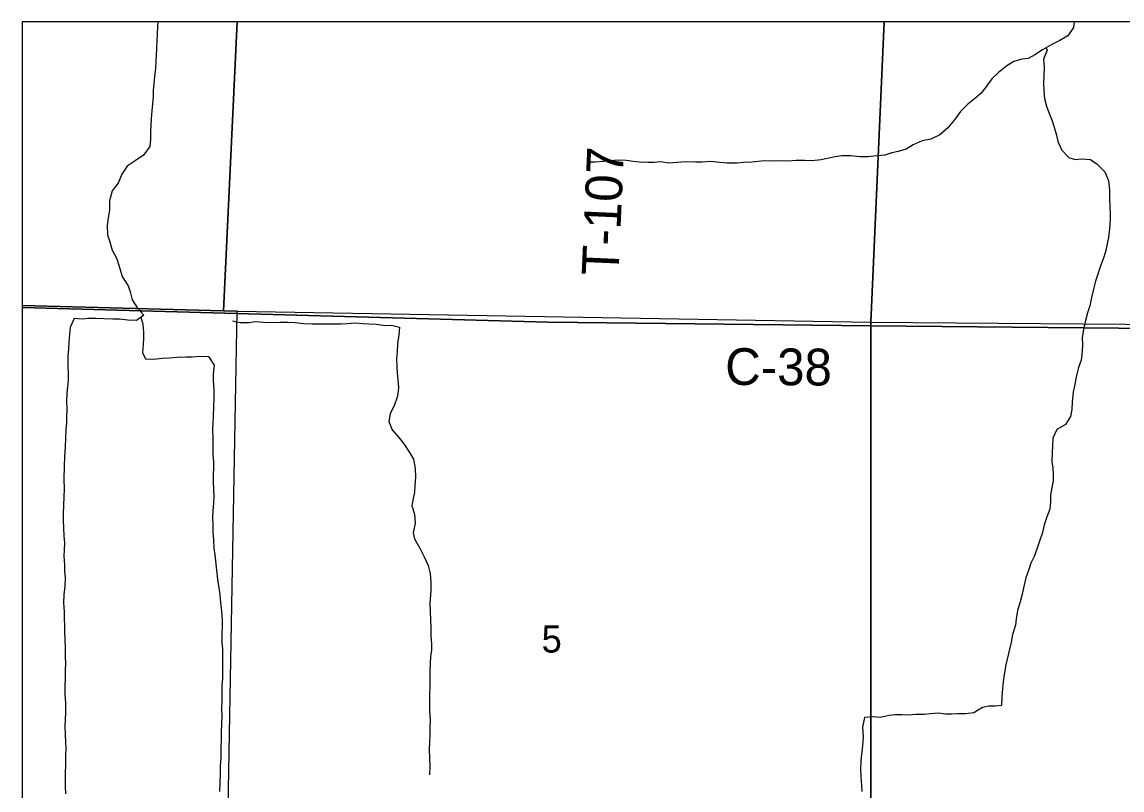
# Model space of a CAD drawing. Extents: x 1772825 to 1773716, y 1138558 to 1139032.
# Drawn here: x 1772825.358 to 1772826.207, y 1138563.767 to 1138564.359 of the extents above; entities that cross this region are included whole.
import ezdxf

# ---------------------------------------------------------------- set-up
doc = ezdxf.new("R2010")
doc.units = 0
for name, color, linetype in [('GM_X_County_Road_Text', 7, 'Continuous'), ('GM_X_Minor_River', 7, 'Continuous'), ('GM_X_Section', 7, 'Continuous'), ('GM_X_Section_Text', 7, 'Continuous'), ('GM_X_Township', 7, 'Continuous'), ('GM_X_Township_Road_Text', 7, 'Continuous')]:
    doc.layers.add(name, color=color, linetype=linetype)

msp = doc.modelspace()

# ---------------------------------------------------------------- linework, layer by layer
at = {"layer": 'GM_X_Minor_River'}
for points in [[(1772825.46264, 1138564.35945), (1772825.46245, 1138564.35612), (1772825.46224, 1138564.35005), (1772825.46202, 1138564.34493), (1772825.46162, 1138564.33868), (1772825.46141, 1138564.33394), (1772825.4612, 1138564.329), (1772825.4608, 1138564.32389), (1772825.4602, 1138564.31706), (1772825.45961, 1138564.31194), (1772825.45921, 1138564.30663), (1772825.459, 1138564.30189), (1772825.45859, 1138564.29639), (1772825.458, 1138564.2909), (1772825.45759, 1138564.28464), (1772825.45738, 1138564.2799), (1772825.45698, 1138564.27497), (1772825.45715, 1138564.26909), (1772825.45656, 1138564.2634), (1772825.4516, 1138564.25678), (1772825.44533, 1138564.25226), (1772825.43906, 1138564.24812), (1772825.43486, 1138564.24207), (1772825.43199, 1138564.23506), (1772825.42741, 1138564.22902), (1772825.4253, 1138564.22144), (1772825.42546, 1138564.21423), (1772825.42448, 1138564.20817), (1772825.42351, 1138564.20229)], [(1772826.16967, 1138564.35945), (1772826.16904, 1138564.35523), (1772826.16484, 1138564.3488), (1772826.15857, 1138564.34522), (1772826.1523, 1138564.34203), (1772826.14527, 1138564.33789), (1772826.13939, 1138564.33412), (1772826.13407, 1138564.3313), (1772826.12933, 1138564.33076), (1772826.12307, 1138564.32889), (1772826.11756, 1138564.3255), (1772826.11128, 1138564.32041), (1772826.10614, 1138564.31569), (1772826.10138, 1138564.30927), (1772826.09757, 1138564.30417), (1772826.09262, 1138564.3002), (1772826.08768, 1138564.29606), (1772826.08197, 1138564.29039), (1772826.07739, 1138564.28397), (1772826.07206, 1138564.27773), (1772826.06598, 1138564.27226), (1772826.05914, 1138564.26907), (1772826.05231, 1138564.26777), (1772826.04548, 1138564.26458), (1772826.03997, 1138564.26138), (1772826.0339, 1138564.25951), (1772826.02897, 1138564.2584), (1772826.02365, 1138564.25672), (1772826.0174, 1138564.25618), (1772826.01038, 1138564.25545), (1772826.00451, 1138564.25529), (1772825.99712, 1138564.25609), (1772825.9903, 1138564.25612), (1772825.98518, 1138564.25538), (1772825.98025, 1138564.25427), (1772825.97437, 1138564.25297), (1772825.96736, 1138564.25224), (1772825.96167, 1138564.25246), (1772825.95504, 1138564.25249), (1772825.94898, 1138564.25195), (1772825.94386, 1138564.25217), (1772825.93742, 1138564.25201), (1772825.93041, 1138564.25223), (1772825.92093, 1138564.25114), (1772825.91449, 1138564.25098), (1772825.90975, 1138564.25043), (1772825.90198, 1138564.25047), (1772825.89611, 1138564.25107), (1772825.88967, 1138564.25167), (1772825.88246, 1138564.25132), (1772825.87754, 1138564.25115)], [(1772826.14805, 1138564.33953), (1772826.14868, 1138564.33768), (1772826.146, 1138564.33068), (1772826.14635, 1138564.32423), (1772826.14633, 1138564.31797), (1772826.14592, 1138564.31247), (1772826.14609, 1138564.30621), (1772826.14663, 1138564.30033), (1772826.14831, 1138564.29444), (1772826.14999, 1138564.28969), (1772826.15262, 1138564.28304), (1772826.1543, 1138564.27829), (1772826.15598, 1138564.27221), (1772826.1571, 1138564.26708), (1772826.1601, 1138564.26062), (1772826.16557, 1138564.2549), (1772826.17049, 1138564.25336), (1772826.17523, 1138564.25372), (1772826.18224, 1138564.25331), (1772826.18734, 1138564.24968), (1772826.19338, 1138564.24377), (1772826.19619, 1138564.23712), (1772826.19692, 1138564.22991), (1772826.19689, 1138564.22308), (1772826.19705, 1138564.21663), (1772826.19741, 1138564.21169), (1772826.19739, 1138564.20695), (1772826.19679, 1138564.20013), (1772826.19619, 1138564.19311), (1772826.19503, 1138564.18819), (1772826.19406, 1138564.18307), (1772826.19252, 1138564.17795), (1772826.18965, 1138564.17038), (1772826.18792, 1138564.16489), (1772826.186, 1138564.1594), (1772826.18465, 1138564.15333), (1772826.18311, 1138564.14689), (1772826.18175, 1138564.14045), (1772826.18002, 1138564.13495), (1772826.17829, 1138564.12908), (1772826.17675, 1138564.12226), (1772826.17577, 1138564.11563), (1772826.17594, 1138564.11069), (1772826.17573, 1138564.10538), (1772826.17494, 1138564.09856), (1772826.17302, 1138564.09288), (1772826.17148, 1138564.08663), (1772826.17012, 1138564.07999), (1772826.16896, 1138564.07374), (1772826.16798, 1138564.06615), (1772826.16776, 1138564.06028), (1772826.16679, 1138564.05497), (1772826.16298, 1138564.04873), (1772826.15633, 1138564.04497), (1772826.15308, 1138564.03834), (1772826.15286, 1138564.03265), (1772826.15265, 1138564.02715), (1772826.15243, 1138564.02032), (1772826.15317, 1138564.0152), (1772826.15353, 1138564.01045), (1772826.15332, 1138564.00533), (1772826.15235, 1138564.00003), (1772826.15137, 1138563.99415), (1772826.15135, 1138563.98903), (1772826.15076, 1138563.98334), (1772826.14827, 1138563.97672), (1772826.14635, 1138563.97122), (1772826.14519, 1138563.96554), (1772826.14288, 1138563.95872), (1772826.14097, 1138563.95323), (1772826.13866, 1138563.94698), (1772826.13618, 1138563.94187), (1772826.13464, 1138563.93676), (1772826.13234, 1138563.93032), (1772826.1308, 1138563.92387), (1772826.12944, 1138563.91781), (1772826.1279, 1138563.91194), (1772826.12598, 1138563.90512), (1772826.125, 1138563.89867), (1772826.12423, 1138563.89393), (1772826.12211, 1138563.88674), (1772826.12095, 1138563.88086), (1772826.11689, 1138563.86324), (1772826.11573, 1138563.85585), (1772826.11494, 1138563.85016), (1772826.11435, 1138563.84504), (1772826.11376, 1138563.83821), (1772826.11354, 1138563.83195), (1772826.10861, 1138563.83141), (1772826.10387, 1138563.83143), (1772826.09894, 1138563.83032), (1772826.09229, 1138563.82636), (1772826.08566, 1138563.82545), (1772826.07978, 1138563.82548), (1772826.07505, 1138563.82531), (1772826.07031, 1138563.82533), (1772826.065, 1138563.82593), (1772826.05875, 1138563.82539), (1772826.05401, 1138563.82503), (1772826.04738, 1138563.82506), (1772826.04169, 1138563.82433)], [(1772825.87754, 1138564.25115), (1772825.87034, 1138564.25157), (1772825.86332, 1138564.25103), (1772825.85669, 1138564.25049), (1772825.85063, 1138564.25147), (1772825.8457, 1138564.25093), (1772825.84059, 1138564.25095), (1772825.83434, 1138564.25136), (1772825.82941, 1138564.25176), (1772825.82411, 1138564.25255), (1772825.81748, 1138564.25277), (1772825.80648, 1138564.25168), (1772825.80004, 1138564.25114), (1772825.7936, 1138564.25136)], [(1772825.42351, 1138564.20229), (1772825.42386, 1138564.19508), (1772825.42554, 1138564.18976), (1772825.42741, 1138564.1833), (1772825.43117, 1138564.17665), (1772825.43341, 1138564.16924), (1772825.43509, 1138564.16297), (1772825.4398, 1138564.15593), (1772825.44129, 1138564.15118), (1772825.44297, 1138564.1451), (1772825.44711, 1138564.13863), (1772825.45182, 1138564.13311), (1772825.44612, 1138564.12896), (1772825.43968, 1138564.12918), (1772825.43324, 1138564.12997), (1772825.42794, 1138564.13), (1772825.42112, 1138564.13022), (1772825.41486, 1138564.13063), (1772825.40899, 1138564.13066), (1772825.40425, 1138564.13011), (1772825.39819, 1138564.13071), (1772825.39513, 1138564.12352), (1772825.39454, 1138564.1184), (1772825.39413, 1138564.11214), (1772825.39373, 1138564.1074), (1772825.39314, 1138564.10095), (1772825.3933, 1138564.0945), (1772825.39365, 1138564.08767), (1772825.39363, 1138564.08293), (1772825.39304, 1138564.07781), (1772825.39245, 1138564.07288), (1772825.39223, 1138564.067), (1772825.39239, 1138564.06036), (1772825.39218, 1138564.05505), (1772825.39216, 1138564.04993), (1772825.39176, 1138564.04519), (1772825.39154, 1138564.03798), (1772825.39132, 1138564.03173), (1772825.39072, 1138564.02376), (1772825.39031, 1138564.01656), (1772825.39027, 1138564.0065), (1772825.39043, 1138563.9991), (1772825.39021, 1138563.99285), (1772825.38999, 1138563.9864), (1772825.38977, 1138563.97957), (1772825.38975, 1138563.97464), (1772825.38992, 1138563.96913), (1772825.39027, 1138563.96287), (1772825.39063, 1138563.95756), (1772825.39041, 1138563.95206), (1772825.3902, 1138563.94732), (1772825.39074, 1138563.9403), (1772825.39072, 1138563.93556), (1772825.39108, 1138563.93024), (1772825.39086, 1138563.92398), (1772825.39007, 1138563.91735), (1772825.39005, 1138563.91128), (1772825.3904, 1138563.90407), (1772825.39056, 1138563.89857), (1772825.39073, 1138563.89382), (1772825.39071, 1138563.88908), (1772825.39106, 1138563.88301), (1772825.39122, 1138563.87599), (1772825.3912, 1138563.86916), (1772825.39136, 1138563.86423), (1772825.39115, 1138563.8593), (1772825.39113, 1138563.85342), (1772825.39091, 1138563.84602), (1772825.39107, 1138563.84071), (1772825.39142, 1138563.83407), (1772825.39158, 1138563.82629), (1772825.39118, 1138563.82079), (1772825.39097, 1138563.81586), (1772825.39132, 1138563.80922), (1772825.39148, 1138563.8039), (1772825.39165, 1138563.79878), (1772825.39144, 1138563.79347), (1772825.39141, 1138563.7855), (1772825.39119, 1138563.78019), (1772825.39117, 1138563.77507), (1772825.39115, 1138563.76976), (1772825.3915, 1138563.76369)], [(1772825.44961, 1138564.1315), (1772825.45123, 1138564.12628), (1772825.45158, 1138564.12002), (1772825.45156, 1138564.11528), (1772825.45135, 1138564.11054), (1772825.45094, 1138564.10447), (1772825.4532, 1138564.09953), (1772825.45964, 1138564.09912), (1772825.46608, 1138564.09985), (1772825.47139, 1138564.1002), (1772825.47764, 1138564.10074), (1772825.48428, 1138564.1009), (1772825.48921, 1138564.10106), (1772825.49565, 1138564.10141), (1772825.50171, 1138564.10138), (1772825.50604, 1138564.09454), (1772825.50544, 1138564.08771), (1772825.50542, 1138564.08259), (1772825.50596, 1138564.07557), (1772825.50593, 1138564.06912), (1772825.50571, 1138564.06229), (1772825.5053, 1138564.05527), (1772825.50509, 1138564.05053), (1772825.50488, 1138564.04408), (1772825.50504, 1138564.03858), (1772825.50501, 1138564.03194), (1772825.50518, 1138564.02511), (1772825.50553, 1138564.02018), (1772825.5057, 1138564.01544), (1772825.50549, 1138564.01013), (1772825.50528, 1138564.00539), (1772825.50563, 1138563.99837), (1772825.5058, 1138563.99343), (1772825.50559, 1138563.98831), (1772825.50518, 1138563.98186), (1772825.50497, 1138563.97693), (1772825.50513, 1138563.97124), (1772825.50511, 1138563.96593), (1772825.50565, 1138563.95948), (1772825.506, 1138563.95341), (1772825.50655, 1138563.94809), (1772825.50802, 1138563.93632), (1772825.50874, 1138563.92911), (1772825.50985, 1138563.92266), (1772825.5104, 1138563.91753), (1772825.51113, 1138563.91108), (1772825.51186, 1138563.90482), (1772825.5124, 1138563.89742), (1772825.51238, 1138563.89267), (1772825.51197, 1138563.88718), (1772825.51214, 1138563.88054), (1772825.51249, 1138563.8756), (1772825.51247, 1138563.86953), (1772825.51263, 1138563.86384), (1772825.51259, 1138563.85284), (1772825.51199, 1138563.84734), (1772825.51197, 1138563.84241), (1772825.51213, 1138563.83596), (1772825.51192, 1138563.82913), (1772825.51208, 1138563.82401), (1772825.51186, 1138563.81699), (1772825.51165, 1138563.81206), (1772825.51144, 1138563.8058), (1772825.51122, 1138563.79916), (1772825.51138, 1138563.79157), (1772825.51078, 1138563.78513), (1772825.51075, 1138563.77887), (1772825.51054, 1138563.77204), (1772825.51032, 1138563.76559)], [(1772825.52021, 1138564.1288), (1772825.52627, 1138564.12763), (1772825.5329, 1138564.1276), (1772825.53802, 1138564.12834), (1772825.54427, 1138564.12774), (1772825.55033, 1138564.12752), (1772825.55697, 1138564.12787), (1772825.56265, 1138564.12765), (1772825.56871, 1138564.12743), (1772825.57496, 1138564.12683), (1772825.58178, 1138564.12642), (1772825.58804, 1138564.12658), (1772825.60414, 1138564.12651), (1772825.60888, 1138564.12667), (1772825.61495, 1138564.12721), (1772825.62082, 1138564.12681), (1772825.62574, 1138564.1264), (1772825.63124, 1138564.12619), (1772825.63824, 1138564.1252), (1772825.64298, 1138564.12556), (1772825.64904, 1138564.12401), (1772825.64863, 1138564.11795), (1772825.64747, 1138564.11112), (1772825.64744, 1138564.10486), (1772825.64685, 1138564.09975), (1772825.64701, 1138564.09311), (1772825.64737, 1138564.08836), (1772825.64773, 1138564.08343), (1772825.64846, 1138564.07697), (1772825.64748, 1138564.07053), (1772825.64537, 1138564.0639), (1772825.64193, 1138564.05709), (1772825.64096, 1138564.05121), (1772825.64358, 1138564.04475), (1772825.64867, 1138564.03866), (1772825.65244, 1138564.0339), (1772825.65677, 1138564.02724), (1772825.65997, 1138564.0221), (1772825.66127, 1138564.0147), (1772825.66143, 1138564.00806), (1772825.66102, 1138564.00161), (1772825.66062, 1138563.99668), (1772825.65965, 1138563.99156), (1772825.65868, 1138563.98588), (1772825.66074, 1138563.97961), (1772825.66127, 1138563.97258), (1772825.65973, 1138563.96519), (1772825.66065, 1138563.96045), (1772825.66479, 1138563.95322), (1772825.66817, 1138563.94656), (1772825.67137, 1138563.93991), (1772825.67267, 1138563.93383), (1772825.67321, 1138563.92719), (1772825.67337, 1138563.92074), (1772825.67257, 1138563.9105), (1772825.67273, 1138563.90462), (1772825.67308, 1138563.89779), (1772825.67325, 1138563.89191), (1772825.67341, 1138563.88546), (1772825.67395, 1138563.87938), (1772825.67393, 1138563.87464), (1772825.67315, 1138563.86971), (1772825.67275, 1138563.86478), (1772825.67253, 1138563.85834), (1772825.6724, 1138563.82799), (1772825.67275, 1138563.82059), (1772825.67254, 1138563.8149), (1772825.67251, 1138563.80864), (1772825.6723, 1138563.8037), (1772825.67208, 1138563.79764), (1772825.67225, 1138563.79156), (1772825.6726, 1138563.78511), (1772825.67238, 1138563.77848)], [(1772826.04169, 1138563.82433), (1772826.03658, 1138563.82473), (1772826.03165, 1138563.82457), (1772826.02691, 1138563.82421), (1772826.01989, 1138563.82273), (1772826.0144, 1138563.82313), (1772826.00796, 1138563.82259), (1772826.00641, 1138563.8152), (1772826.00676, 1138563.8078), (1772826.00635, 1138563.80079), (1772826.00556, 1138563.79396), (1772826.00516, 1138563.78922), (1772826.00475, 1138563.78239), (1772826.00511, 1138563.77727), (1772826.00546, 1138563.77025), (1772826.00582, 1138563.76551)]]:
    msp.add_lwpolyline(points, dxfattribs=at)
at = {"layer": 'GM_X_Section'}
for p, q in [((1772826.02299, 1138564.35945), (1772825.52402, 1138564.35945)), ((1772826.5321, 1138564.35945), (1772826.02299, 1138564.35945)), ((1772825.35791, 1138564.14068), (1772825.35791, 1138563.65686))]:
    msp.add_line(p, q, dxfattribs=at)
for points in [[(1772825.52402, 1138564.35945), (1772825.35791, 1138564.35945), (1772825.35791, 1138564.14068)], [(1772825.35791, 1138564.14068), (1772825.51345, 1138564.13656), (1772825.52402, 1138564.35945)], [(1772825.52402, 1138564.35945), (1772825.51345, 1138564.13656), (1772825.52387, 1138564.13628), (1772826.01263, 1138564.12772), (1772826.02299, 1138564.35945)], [(1772826.02299, 1138564.35945), (1772826.01263, 1138564.12772), (1772826.50366, 1138564.12386), (1772826.51938, 1138564.12393), (1772826.5321, 1138564.35945)], [(1772825.35791, 1138563.65686), (1772825.51518, 1138563.65396), (1772825.52387, 1138564.13628), (1772825.51345, 1138564.13656), (1772825.35791, 1138564.14068)]]:
    msp.add_lwpolyline(points, dxfattribs=at)
for points in [[(1772825.52387, 1138564.13628), (1772826.01263, 1138564.12772), (1772826.01279, 1138563.64058), (1772825.51518, 1138563.65396)], [(1772826.50366, 1138564.12386), (1772826.49778, 1138563.64814), (1772826.01279, 1138563.64058), (1772826.01263, 1138564.12772)]]:
    msp.add_lwpolyline(points, close=True, dxfattribs=at)
at = {"layer": 'GM_X_Township'}
msp.add_line((1772825.35791, 1138564.139), (1772825.35791, 1138561.13797), dxfattribs=at)
for points in [[(1772828.04209, 1138564.35945), (1772825.35791, 1138564.35945), (1772825.35791, 1138564.139)], [(1772825.35791, 1138564.139), (1772825.51433, 1138564.13469), (1772825.76373, 1138564.12775), (1772826.01279, 1138564.12485), (1772826.2589, 1138564.1226), (1772826.26734, 1138564.12259), (1772826.50566, 1138564.12172), (1772826.51832, 1138564.12155), (1772827.00064, 1138564.13059), (1772827.02571, 1138564.13101), (1772827.29014, 1138564.13627), (1772827.56011, 1138564.14366), (1772828.02917, 1138564.14907), (1772828.04209, 1138564.35945)], [(1772827.00064, 1138564.13059), (1772826.51832, 1138564.12155), (1772826.50566, 1138564.12172), (1772826.26734, 1138564.12259), (1772826.2589, 1138564.1226), (1772826.01279, 1138564.12485), (1772825.76373, 1138564.12775), (1772825.51433, 1138564.13469), (1772825.35791, 1138564.139)]]:
    msp.add_lwpolyline(points, dxfattribs=at)

# ---------------------------------------------------------------- texts
at = {"layer": 'GM_X_County_Road_Text'}
msp.add_text('C-38', height=0.028409, rotation=359.65483, dxfattribs=at).set_placement((1772825.90031, 1138564.07934))
at = {"layer": 'GM_X_Section_Text'}
msp.add_text('5', height=0.02093, rotation=0.00001, dxfattribs=at).set_placement((1772825.75876, 1138563.87274))
at = {"layer": 'GM_X_Township_Road_Text'}
msp.add_text('T-107', height=0.028409, rotation=87.47454, dxfattribs=at).set_placement((1772825.81803, 1138564.16317))

doc.saveas('drawing.dxf')
